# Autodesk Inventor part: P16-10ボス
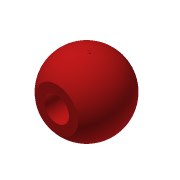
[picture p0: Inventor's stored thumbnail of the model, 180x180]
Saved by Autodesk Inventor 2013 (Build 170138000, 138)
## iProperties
Created: 2008-07
Part Number: P16-10ボス
Document SubType Name: Modeling
Designer: y-shimohigashi
Density: 1 g/cm^3
Material: 一般
Author: y-shimohigashi
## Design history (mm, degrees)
sketch "スケッチ1"
  geometry: L1 (0, 12)-(0, 3.253); L2 (0, 3.253)-(4, 3.253); L3 (4, 3.253)-(4, -9.747); L4 (4, -9.747)-(7, -9.747); A1 r 12 centre (0, 0) between (7, -9.747) and (0, 12); 1 further point
  constraints: 8 end point, 2 parallel, 2 point on circle, 1 centre point, 1 coincident, 1 perpendicular, 1 point on line, 1 vertical
  dimensions: "d0" = 4 distance of L1.end L2.end; "d1" = 3 distance of L3.end L4.end; "d2" = 13 distance of L2.end L3.end; "d3" = 12 radius of A1
revolve "回転1" sketch "スケッチ1" stored, may be unused: angle "d4" = 90 deg
node "ソリッド1"
node "ソリッド ボディ"
node "サーフェス ボディ"
